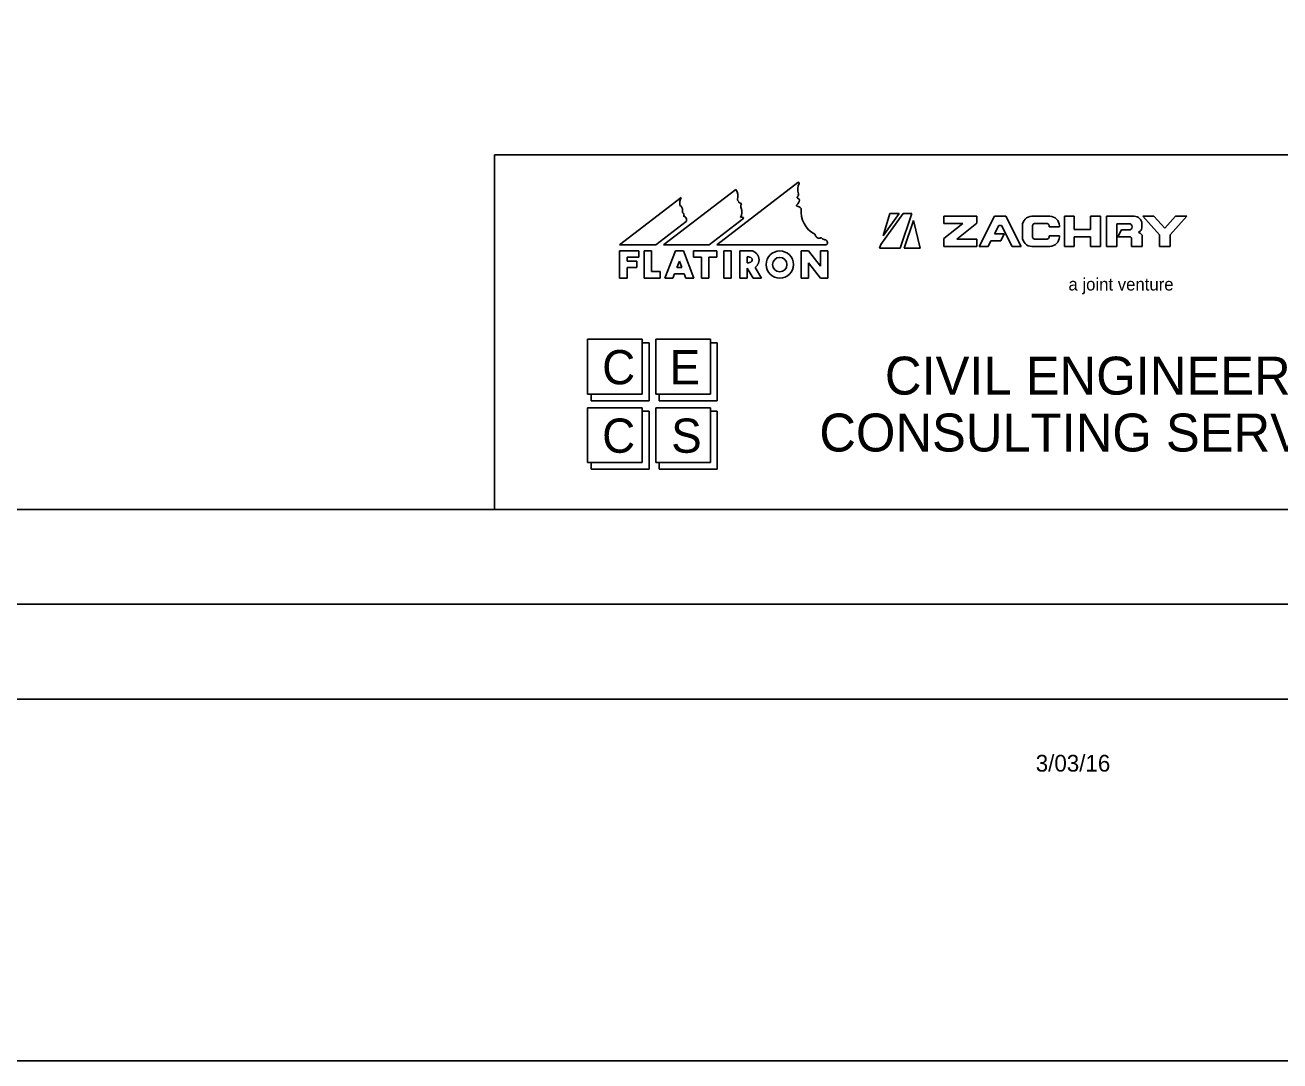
# Model space of a CAD drawing. Extents: x -2251 to 10196, y -13470 to 1199.
# Drawn here: x 1189.9 to 1520.8, y -4546.1 to -4272.9 of the extents above; entities that cross this region are included whole.
import ezdxf

# ---------------------------------------------------------------- set-up
doc = ezdxf.new("R2010")
doc.units = 0
for name, color, linetype in [('Level 3', 7, 'Continuous'), ('RD_SHT_Bndy', 7, 'Continuous'), ('RD_SHT_Iplotshp', 7, 'Continuous'), ('RD_SHT_Logo', 7, 'Continuous'), ('RD_SHT_Misc1', 7, 'Continuous'), ('RD_SHT_Snap', 7, 'Continuous'), ('RD_SHT_TX', 7, 'Continuous'), ('RD_TX_Misc1', 7, 'Continuous')]:
    doc.layers.add(name, color=color, linetype=linetype)

msp = doc.modelspace()

# ---------------------------------------------------------------- linework, layer by layer
at = {"layer": 'Level 3'}
msp.add_line((1465.07, -4363.99), (1465.07, -4363.99), dxfattribs=at)
msp.add_line((1465.07, -4363.99), (1465.07, -4363.99), dxfattribs=at)
msp.add_line((1465.07, -4363.99), (1465.07, -4363.99), dxfattribs=at)
msp.add_line((1465.07, -4363.99), (1465.07, -4363.99), dxfattribs=at)
at = {"layer": 'RD_SHT_Bndy'}
for p, q in [((103.1, -4400.65), (1778.1, -4400.65)), ((1791.65, -4425.65), (31.65, -4425.65)), ((1791.6, -4450.7), (31.6, -4450.65))]:
    msp.add_line(p, q, dxfattribs=at)
at = {"layer": 'RD_SHT_Iplotshp'}
msp.add_lwpolyline([(-3.35, -3325.65), (1796.65, -3325.65), (1796.65, -4425.65), (-3.35, -4425.65)], close=True, dxfattribs=at)
at = {"layer": 'RD_SHT_Logo'}
for p, q in [((1372.32, -4330.86), (1393.74, -4314.44)), ((1346.7, -4330.86), (1362.98, -4318.38)), ((1377.35, -4316.27), (1358.31, -4330.86)), ((1364.27, -4324.74), (1356.29, -4330.86)), ((1370.3, -4330.86), (1379.48, -4323.82)), ((1415.56, -4330.77), (1421.47, -4322.59)), ((1420.48, -4322.59), (1416.24, -4328.47)), ((1416.24, -4328.47), (1417.96, -4322.59)), ((1417.96, -4322.59), (1420.48, -4322.59)), ((1423.82, -4322.59), (1420.68, -4331.76)), ((1421.47, -4322.59), (1423.82, -4322.59)), ((1424.24, -4324.44), (1421.74, -4331.76)), ((1425.99, -4331.76), (1424.24, -4324.44)), ((1440.93, -4323.35), (1432.22, -4323.35)), ((1432.22, -4323.35), (1432.22, -4325.3)), ((1440.93, -4325.16), (1440.93, -4323.35)), ((1445.58, -4323.35), (1441.53, -4331.3)), ((1448.58, -4323.35), (1445.58, -4323.35)), ((1452.63, -4331.3), (1448.58, -4323.35)), ((1455.44, -4323.35), (1460.18, -4323.35)), ((1466.62, -4323.35), (1464.02, -4323.35)), ((1464.02, -4323.35), (1464.02, -4331.3)), ((1466.62, -4326.8), (1466.62, -4323.35)), ((1470.9, -4323.35), (1470.9, -4326.8)), ((1473.51, -4323.35), (1470.9, -4323.35)), ((1473.5, -4331.3), (1473.51, -4323.35)), ((1482.43, -4323.35), (1475.13, -4323.35)), ((1475.13, -4323.35), (1475.13, -4331.3)), ((1484.68, -4323.35), (1487.64, -4323.35)), ((1489.08, -4328.24), (1484.68, -4323.35)), ((1487.64, -4323.35), (1490.48, -4326.51)), ((1490.48, -4326.51), (1493.32, -4323.35)), ((1496.28, -4323.35), (1491.88, -4328.24)), ((1493.32, -4323.35), (1496.28, -4323.35)), ((1437.2, -4325.3), (1432.22, -4329.24)), ((1432.22, -4325.3), (1437.2, -4325.3)), ((1435.63, -4329.35), (1440.93, -4325.16)), ((1445.57, -4327.99), (1446.71, -4325.75)), ((1448.15, -4327.99), (1445.57, -4327.99)), ((1446.71, -4325.75), (1447.44, -4325.75)), ((1447.23, -4329.79), (1448.15, -4327.99)), ((1447.44, -4325.75), (1450.27, -4331.3)), ((1452.94, -4328.8), (1452.94, -4325.85)), ((1455.64, -4325.8), (1455.64, -4328.85)), ((1459.48, -4325.3), (1456.14, -4325.3)), ((1459.98, -4326.15), (1459.98, -4325.8)), ((1462.68, -4326.15), (1459.98, -4326.15)), ((1462.68, -4325.85), (1462.68, -4326.15)), ((1470.9, -4326.8), (1466.62, -4326.8)), ((1477.83, -4331.3), (1477.83, -4325.31)), ((1477.83, -4325.31), (1481.07, -4325.31)), ((1479.03, -4326.97), (1478.11, -4328.77)), ((1481.07, -4326.97), (1479.03, -4326.97)), ((1483.68, -4327.6), (1483.68, -4327.47)), ((1484.43, -4326.36), (1484.43, -4325.35)), ((1489.08, -4331.3), (1489.08, -4328.24)), ((1491.88, -4328.24), (1491.88, -4331.3)), ((1356.29, -4330.86), (1346.7, -4330.86)), ((1358.31, -4330.86), (1370.3, -4330.86)), ((1401.19, -4330.86), (1372.32, -4330.86)), ((1415.27, -4331.76), (1415.56, -4330.77)), ((1432.22, -4329.24), (1432.22, -4331.3)), ((1432.22, -4331.3), (1440.93, -4331.3)), ((1440.93, -4329.35), (1435.63, -4329.35)), ((1440.93, -4331.3), (1440.93, -4329.35)), ((1441.53, -4331.3), (1443.88, -4331.3)), ((1443.88, -4331.3), (1444.65, -4329.79)), ((1444.65, -4329.79), (1447.23, -4329.79)), ((1450.27, -4331.3), (1452.63, -4331.3)), ((1460.18, -4331.3), (1455.44, -4331.3)), ((1456.14, -4329.35), (1459.48, -4329.35)), ((1459.98, -4328.5), (1462.68, -4328.5)), ((1459.98, -4328.85), (1459.98, -4328.5)), ((1462.68, -4328.5), (1462.68, -4328.8)), ((1464.02, -4331.3), (1466.62, -4331.3)), ((1466.62, -4331.3), (1466.62, -4328.8)), ((1466.62, -4328.8), (1470.9, -4328.8)), ((1470.9, -4328.8), (1470.9, -4331.3)), ((1470.9, -4331.3), (1473.5, -4331.3)), ((1475.13, -4331.3), (1477.83, -4331.3)), ((1478.11, -4328.77), (1481.24, -4328.77)), ((1481.74, -4329.27), (1481.74, -4331.3)), ((1481.74, -4331.3), (1484.54, -4331.3)), ((1484.54, -4331.3), (1484.54, -4328.76)), ((1491.88, -4331.3), (1489.08, -4331.3)), ((1346.72, -4339.7), (1346.72, -4332.5)), ((1346.72, -4332.5), (1351.82, -4332.5)), ((1351.82, -4334.15), (1348.67, -4334.15)), ((1348.67, -4334.15), (1348.67, -4335.21)), ((1351.82, -4332.5), (1351.82, -4334.15)), ((1355.12, -4332.5), (1353.17, -4332.5)), ((1353.17, -4332.5), (1353.17, -4339.7)), ((1355.12, -4337.9), (1355.12, -4332.5)), ((1361.42, -4332.5), (1358.65, -4339.71)), ((1363.52, -4332.5), (1361.42, -4332.5)), ((1366.28, -4339.71), (1363.52, -4332.5)), ((1366.22, -4334.15), (1366.22, -4332.5)), ((1366.22, -4332.5), (1372.37, -4332.5)), ((1368.32, -4334.15), (1366.22, -4334.15)), ((1368.32, -4339.71), (1368.32, -4334.15)), ((1372.37, -4334.15), (1370.27, -4334.15)), ((1370.27, -4334.15), (1370.27, -4339.71)), ((1372.37, -4332.5), (1372.37, -4334.15)), ((1374.17, -4339.71), (1374.17, -4332.5)), ((1374.17, -4332.5), (1376.12, -4332.5)), ((1376.12, -4332.5), (1376.12, -4339.71)), ((1381.8, -4332.5), (1378.38, -4332.5)), ((1378.38, -4332.5), (1378.38, -4339.71)), ((1380.33, -4335.66), (1380.33, -4334.01)), ((1396.52, -4332.5), (1394.57, -4332.5)), ((1394.57, -4332.5), (1394.57, -4339.71)), ((1399.67, -4336.53), (1396.52, -4332.5)), ((1401.62, -4332.5), (1399.67, -4332.5)), ((1399.67, -4332.5), (1399.67, -4336.53)), ((1401.62, -4339.71), (1401.62, -4332.5)), ((1420.68, -4331.76), (1415.27, -4331.76)), ((1421.74, -4331.76), (1425.99, -4331.76)), ((1348.67, -4335.21), (1351.22, -4335.21)), ((1351.22, -4336.86), (1348.67, -4336.86)), ((1348.67, -4336.86), (1348.67, -4339.7)), ((1351.22, -4335.21), (1351.22, -4336.86)), ((1357.37, -4337.9), (1355.12, -4337.9)), ((1357.37, -4339.71), (1357.37, -4337.9)), ((1361.83, -4336.86), (1362.47, -4335.2)), ((1363.1, -4336.86), (1361.83, -4336.86)), ((1362.47, -4335.2), (1363.1, -4336.86)), ((1380.33, -4339.71), (1380.33, -4337.02)), ((1380.33, -4337.02), (1381.94, -4339.71)), ((1384.16, -4339.71), (1382.43, -4336.82)), ((1396.52, -4339.71), (1396.52, -4335.67)), ((1396.52, -4335.67), (1399.67, -4339.71)), ((1348.67, -4339.7), (1346.72, -4339.7)), ((1353.17, -4339.7), (1357.37, -4339.71)), ((1358.65, -4339.71), (1360.74, -4339.71)), ((1360.74, -4339.71), (1361.2, -4338.51)), ((1361.2, -4338.51), (1363.74, -4338.51)), ((1363.74, -4338.51), (1364.2, -4339.71)), ((1364.2, -4339.71), (1366.28, -4339.71)), ((1370.27, -4339.71), (1368.32, -4339.71)), ((1376.12, -4339.71), (1374.17, -4339.71)), ((1378.38, -4339.71), (1380.33, -4339.71)), ((1381.94, -4339.71), (1384.16, -4339.71)), ((1394.57, -4339.71), (1396.52, -4339.71)), ((1399.67, -4339.71), (1401.62, -4339.71)), ((1352.67, -4355.79), (1338.28, -4355.79)), ((1338.28, -4355.79), (1338.28, -4370.23)), ((1352.67, -4370.23), (1352.67, -4355.79)), ((1352.67, -4355.79), (1352.67, -4370.23)), ((1354.48, -4356.7), (1352.67, -4356.7)), ((1354.48, -4372.03), (1354.48, -4356.7)), ((1370.67, -4355.79), (1356.27, -4355.79)), ((1356.27, -4355.79), (1356.27, -4370.23)), ((1370.67, -4370.23), (1370.67, -4355.79)), ((1370.67, -4355.79), (1370.67, -4370.23)), ((1372.48, -4356.7), (1370.67, -4356.7)), ((1372.48, -4372.03), (1372.48, -4356.7)), ((1338.28, -4370.23), (1352.67, -4370.23)), ((1352.67, -4370.23), (1339.17, -4370.23)), ((1339.17, -4370.23), (1339.17, -4372.03)), ((1356.27, -4370.23), (1370.67, -4370.23)), ((1370.67, -4370.23), (1357.18, -4370.23)), ((1357.18, -4370.23), (1357.18, -4372.03)), ((1352.67, -4373.84), (1338.28, -4373.84)), ((1338.28, -4373.84), (1338.28, -4388.27)), ((1339.17, -4372.03), (1354.48, -4372.03)), ((1352.67, -4388.27), (1352.67, -4373.84)), ((1352.67, -4373.84), (1352.67, -4388.27)), ((1370.67, -4373.84), (1356.27, -4373.84)), ((1356.27, -4373.84), (1356.27, -4388.27)), ((1357.18, -4372.03), (1372.48, -4372.03)), ((1370.67, -4388.27), (1370.67, -4373.84)), ((1370.67, -4373.84), (1370.67, -4388.27)), ((1354.48, -4374.74), (1352.67, -4374.74)), ((1354.48, -4390.07), (1354.48, -4374.74)), ((1372.48, -4374.74), (1370.67, -4374.74)), ((1372.48, -4390.07), (1372.48, -4374.74)), ((1338.28, -4388.27), (1352.67, -4388.27)), ((1352.67, -4388.27), (1339.17, -4388.27)), ((1339.17, -4388.27), (1339.17, -4390.07)), ((1339.17, -4390.07), (1354.48, -4390.07)), ((1356.27, -4388.27), (1370.67, -4388.27)), ((1370.67, -4388.27), (1357.18, -4388.27)), ((1357.18, -4388.27), (1357.18, -4390.07)), ((1357.18, -4390.07), (1372.48, -4390.07))]:
    msp.add_line(p, q, dxfattribs=at)
for radius in [3.6, 1.9]:
    msp.add_circle((1388.95, -4336.1), radius, dxfattribs=at)
for centre, radius, start, end in [((1397.87, -4316.34), 4.17, 156.4699, 195.3053), ((1393.86, -4314.6), 0.2, 336.4699, 127.4657), ((1366.29, -4320.12), 3.74, 152.2252, 185.8662), ((1375.05, -4318.02), 2.89, 342.0343, 37.2653), ((1393.73, -4318.39), 0.2, 129.4079, 246.863), ((1393.13, -4317.66), 0.749, 309.4079, 17.0499), ((1362.1, -4321.62), 1.21, 351.6466, 67.1294), ((1377.99, -4318.97), 0.2, 162.0343, 220.8638), ((1376.86, -4319.95), 1.3, 11.8745, 40.8638), ((1378.32, -4319.64), 0.2, 191.8745, 279.8173), ((1378.44, -4320.33), 0.499, 44.4799, 99.8173), ((1375.8, -4322.18), 3.16, 331.2486, 18.4584), ((1379.5, -4320.72), 0.843, 144.641, 212.5499), ((1378.65, -4320.12), 0.2, 324.641, 44.4799), ((1393.57, -4320.5), 0.2, 133.0036, 262.3069), ((1391.59, -4318.37), 2.7, 313.0036, 343.6807), ((1393.31, -4322.44), 1.76, 45.283, 82.3069), ((1393.27, -4319.47), 0.973, 20.4113, 66.863), ((1394.4, -4321.33), 0.2, 353.8329, 45.283), ((1401.36, -4322.08), 6.8, 173.8329, 242.3928), ((1364.29, -4321.94), 1, 171.6466, 221.9371), ((1363.11, -4323.01), 0.592, 327.6019, 41.9371), ((1363.3, -4324.33), 1.05, 337.4201, 73.1261), ((1378.92, -4324.44), 0.827, 48.0701, 115.7229), ((1455.44, -4325.85), 2.5, 89.9984, 179.9984), ((1460.18, -4325.85), 2.5, 359.9984, 89.9984), ((1482.43, -4325.35), 2, 359.9984, 89.9984), ((1398.12, -4328.28), 0.2, 9.0833, 62.3928), ((1399.35, -4328.09), 1.04, 189.0833, 295.769), ((1456.14, -4325.8), 0.5, 89.9984, 179.9984), ((1459.48, -4325.8), 0.5, 359.9984, 89.9984), ((1481.07, -4326.14), 0.831, 269.9984, 89.9984), ((1483.23, -4326.36), 1.2, 291.95, 359.9984), ((1483.34, -4328.76), 1.2, 359.9984, 73.7977), ((1399.89, -4329.21), 0.2, 33.7112, 115.769), ((1400.89, -4328.54), 1.01, 213.7112, 268.6299), ((1400.86, -4329.74), 0.2, 78.9712, 88.6299), ((1400.75, -4330.3), 0.767, 320.912, 78.9712), ((1401.19, -4330.66), 0.2, 269.9984, 320.912), ((1455.44, -4328.8), 2.5, 179.9984, 269.9984), ((1456.14, -4328.85), 0.5, 179.9984, 269.9984), ((1459.48, -4328.85), 0.5, 269.9984, 359.9984), ((1460.18, -4328.8), 2.5, 269.9984, 359.9984), ((1481.24, -4329.27), 0.5, 359.9984, 89.9984)]:
    msp.add_arc(centre, radius, start, end, dxfattribs=at)
msp.add_ellipse((1380.33, -4334.83), major_axis=(1.36, 0), ratio=0.609965, start_param=4.712389, end_param=7.853982, dxfattribs=at)
msp.add_open_spline([(1382.43, -4336.82), (1382.51, -4336.76), (1382.59, -4336.7), (1382.81, -4336.49), (1382.95, -4336.34), (1383.13, -4336.07), (1383.19, -4335.97), (1383.29, -4335.77), (1383.34, -4335.66), (1383.41, -4335.44), (1383.44, -4335.32), (1383.47, -4335.08), (1383.48, -4334.96), (1383.48, -4334.71), (1383.47, -4334.59), (1383.44, -4334.35), (1383.41, -4334.23), (1383.34, -4334.01), (1383.29, -4333.9), (1383.19, -4333.7), (1383.13, -4333.6), (1382.95, -4333.33), (1382.81, -4333.18), (1382.52, -4332.91), (1382.37, -4332.8), (1382.08, -4332.63), (1381.94, -4332.56), (1381.8, -4332.5)], degree=3, dxfattribs=at)
at = {"layer": 'RD_SHT_Misc1'}
msp.add_lwpolyline([(1796.65, -4425.65), (1796.68, -3325.65), (96.68, -3325.6), (96.65, -4425.6)], close=True, dxfattribs=at)
at = {"layer": 'RD_SHT_Snap'}
msp.add_lwpolyline([(8.15, -3325.65), (1808.15, -3325.65), (1808.15, -4425.65), (8.15, -4425.65)], close=True, dxfattribs=at)
at = {"layer": 'RD_SHT_TX'}
for p, q in [((1313.76, -4400.65), (1313.76, -4307.15)), ((1313.76, -4400.65), (1313.76, -4307.15)), ((1313.76, -4307.15), (1778.1, -4307.15))]:
    msp.add_line(p, q, dxfattribs=at)
at = {"layer": 'RD_TX_Misc1'}
msp.add_lwpolyline([(-127.02, -3244.69), (1914.78, -3244.69), (1914.78, -4546.07), (-127.02, -4546.07)], close=True, dxfattribs=at)

# ---------------------------------------------------------------- texts
at = {"layer": 'RD_SHT_Logo'}
msp.add_text('a joint venture', height=3.3, rotation=359.9984, dxfattribs=at).set_placement((1465.08, -4342.93))
for s, height, p in [('C', 9.02, (1342.11, -4367.66)), ('E', 9.02, (1359.9, -4367.66)), ('CIVIL ENGINEERING', 10, (1416.67, -4370.38)), ('C', 9.02, (1342.11, -4385.71)), ('S', 9.02, (1360.32, -4385.71)), ('CONSULTING SERVICES, INC.', 10, (1399.39, -4385.38))]:
    msp.add_text(s, height=height, dxfattribs=at).set_placement(p)
at = {"layer": 'RD_SHT_TX'}
msp.add_text('3/03/16', height=4.408, dxfattribs=at).set_placement((1456.45, -4469.78))

doc.saveas('drawing.dxf')
